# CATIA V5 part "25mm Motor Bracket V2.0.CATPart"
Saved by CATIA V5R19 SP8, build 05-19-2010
Part number: 25mm Motor Bracket
Definition: 25mm Motor Bracket
Nomenclature: 61802
Source: Unknown
Material "Aluminium": density 2710 kg/m3, Young's modulus 7e+10 Pa, Poisson ratio 0.346, thermal expansion 2.36e-05 1/K
Bounding box of the stored display mesh (mm): x -19 to 19, y -24 to 12.5, z 0 to 3
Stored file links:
  D:\Documents\1_Travail\1 - ac-limoges.fr\ac-limoges.fr\Emmanuel Maynard - STI2D_Turgot\1 - IT-I2D\Activités_IT_Première\IT_3_Abris_bus\Maquettes numériques\Abribus_eleve\25mm Motor Bracket V2.0.CATPart
  C:\Program Files\Dassault Systemes\B19\win_b64\startup\materials\French\Catalog.CATMaterial
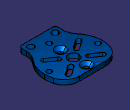
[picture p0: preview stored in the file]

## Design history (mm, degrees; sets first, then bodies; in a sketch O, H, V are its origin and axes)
AxisSystem1: origin (0, 0, 0), X (1, 0, 0), Y (0, 1, 0), Z (0, 0, 1)
Body1 "M4 Tapped Hole1" (main body), material "Aluminium"
  Solid1: solid without history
